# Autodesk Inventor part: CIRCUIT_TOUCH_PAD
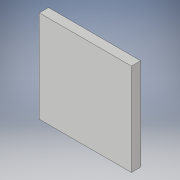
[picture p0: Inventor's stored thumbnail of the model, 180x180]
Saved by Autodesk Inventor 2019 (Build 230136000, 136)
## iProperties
Created: 2020-03
Part Number: CIRCUIT_TOUCH_PAD
Material: Generic
Document SubType Name: Modeling
Designer: Siddharth
Density: 1 g/cm^3
Appearance: Default
Author: Siddharth
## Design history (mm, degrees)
sketch "Sketch1"
  geometry: L1 (0, 0)-(50, 0); L2 (50, 0)-(50, 50); L3 (50, 50)-(0, 50); L4 (0, 50)-(0, 0)
  constraints: 8 end point, 2 parallel, 1 horizontal, 1 perpendicular
  dimensions: "d0" = 50 distance of L3.end L2.end; "d1" = 50 distance of L2.end L1.end
extrude "Extrusion1" new body sketch "Sketch1" distance "d2" = 5; taper "d3" = 0 deg
body "Solid1"
